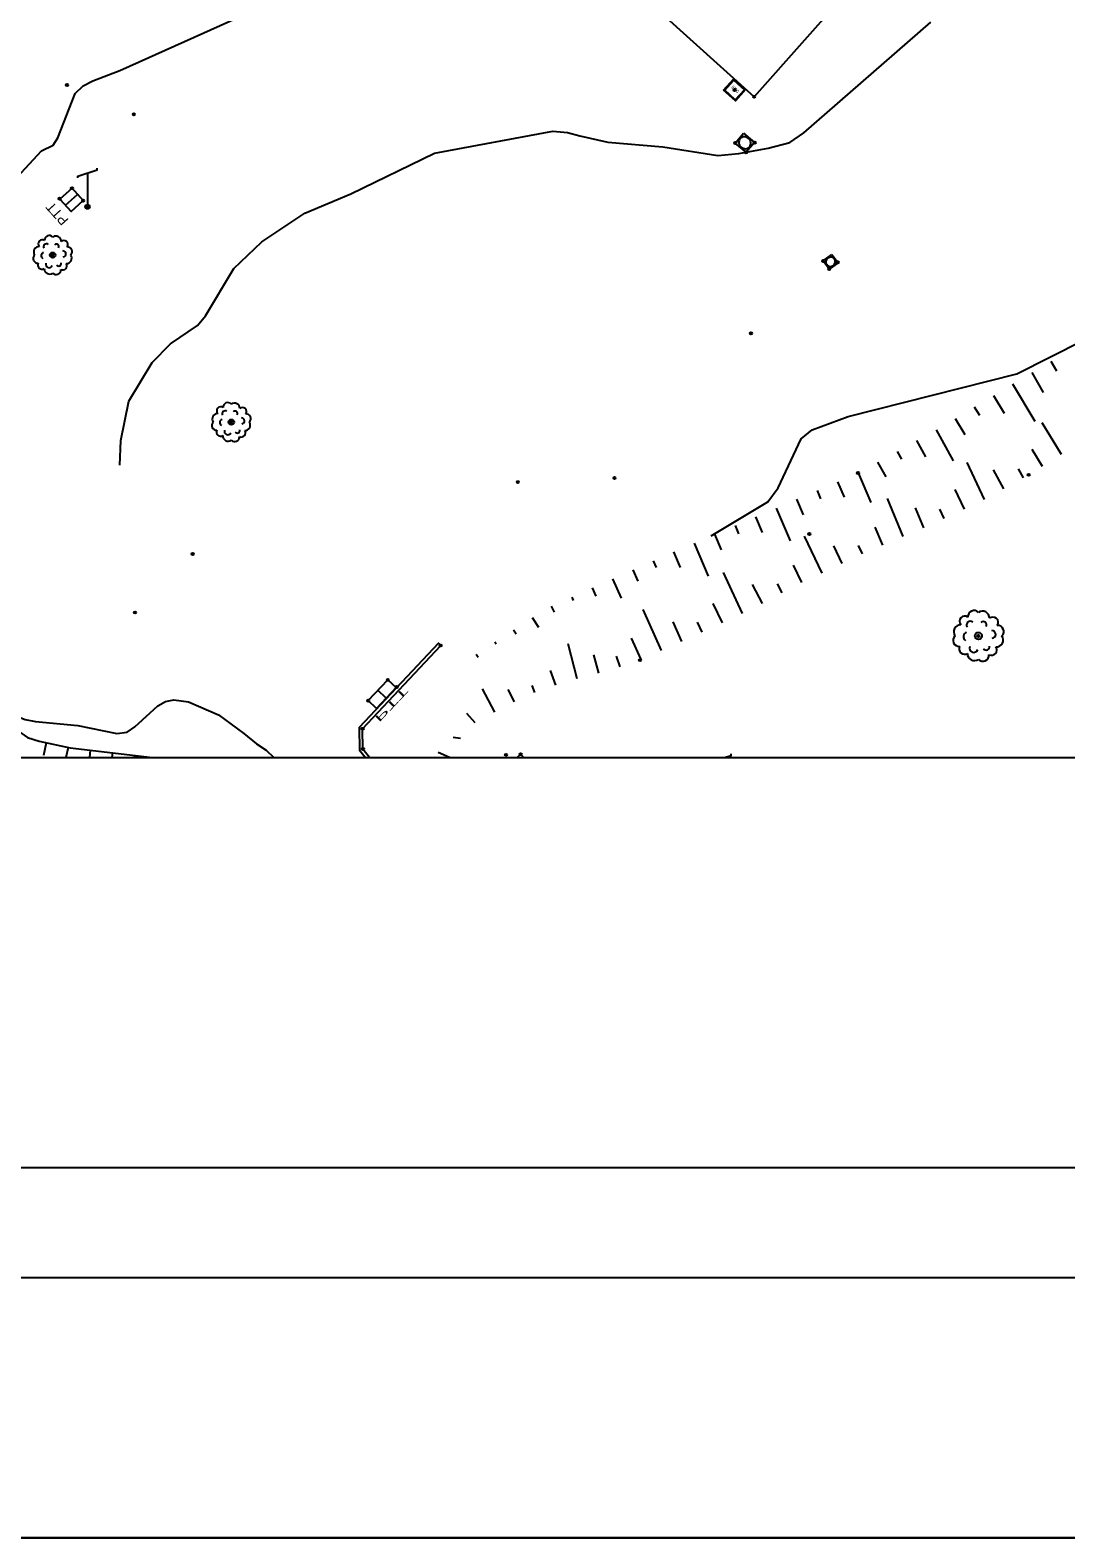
# Model space of a CAD drawing. Extents: x 344013 to 344423, y 298505 to 298795.
# Drawn here: x 344301.3 to 344347.8, y 298504.9 to 298572.5 of the extents above; entities that cross this region are included whole.
import ezdxf

# ---------------------------------------------------------------- set-up
doc = ezdxf.new("R2010")
doc.units = 0
for name, color, linetype in [('Default', 7, 'Continuous'), ('DH_CADRE -CARTOUCHE', 7, 'Continuous'), ('DH_CADRE-CARTOUCHE-NORD', 7, 'Continuous'), ('GO_MUR', 7, 'Continuous'), ('PC_CONCRETE', 7, 'Continuous'), ('RES_ELECTRICITE', 7, 'Continuous'), ('TOPO_COURBE NIVEAU', 7, 'Continuous'), ('TOPO_POINT', 7, 'Continuous'), ('TOPO_TALUS-TERRAIN NATUREL', 7, 'Continuous'), ('VOIRIE_ESPACE VERT', 7, 'Continuous')]:
    doc.layers.add(name, color=color, linetype=linetype)

# ---------------------------------------------------------------- blocks, each defined once
blk = doc.blocks.new('CT2')
at = {"layer": 'Default'}
blk.add_lwpolyline([(0, 0), (1, 0), (1, 1), (0, 1)], close=True, dxfattribs=at)
blk.add_lwpolyline([(0.5, 1), (0.5, 0)], dxfattribs=at)
blk.add_text('PTT', height=0.6, dxfattribs=at).set_placement((-0.3, 1.425))
blk = doc.blocks.new('REG_INC')
at = {"layer": 'Default'}
for p, q in [((0, 1), (1, 1)), ((0, 0), (0, 1)), ((1, 0), (0, 0)), ((1, 1), (1, 0))]:
    blk.add_line(p, q, dxfattribs=at)
for start, end in [(135.0055, 180.0055), (180.0066, 225.0066), (90.0058, 135.0058), (225.0069, 270.0069), (45.0069, 90.0069), (270.0058, 315.0058), (0.0066, 45.0066), (315.0055, 0.0055)]:
    blk.add_arc((0.5, 0.5), 0.44, start, end, dxfattribs=at)
blk = doc.blocks.new('RES_ELECTRICITE')
at = {"layer": 'RES_ELECTRICITE'}
for points in [[(0, 0), (0, 1), (1, 1), (1, 0)], [(0.05, 0.05), (0.05, 0.95), (0.95, 0.95), (0.95, 0.05)]]:
    blk.add_lwpolyline(points, close=True, dxfattribs=at)
blk.add_text('EEC', height=0.2, dxfattribs=at).set_placement((0.237, 0.46))
blk = doc.blocks.new('POINT_DISPLAY')
at = {"layer": 'Default'}
blk.add_circle((0, 0), 0.05, dxfattribs=at)
blk = doc.blocks.new('PTT1')
at = {"layer": 'Default'}
blk.add_line((0, 1.510991), (0, 0.1), dxfattribs=at)
blk.add_lwpolyline([(-0.438601, 1.29169), (-0.438601, 1.36518), (0.438601, 1.656803), (0.438601, 1.730292)], dxfattribs=at)
blk.add_circle((0, 0), 0.1, dxfattribs=at)
blk = doc.blocks.new('ARB1')
at = {"layer": 'Default'}
blk.add_circle((0, 0), 0.122, dxfattribs=at)
for centre, radius, start, end in [((-0.471, 0.503), 0.183, 53.9554, 222.2066), ((-0.153, 0.664), 0.211, 43.6925, 183.5969), ((0.139, 0.613), 0.241, 358.4583, 125.1928), ((0.501, 0.468), 0.183, 325.1444, 131.0175), ((-0.613, 0.139), 0.241, 88.4583, 215.1928), ((-0.373, -0.024), 0.149, 103.7092, 242.3465), ((-0.276, 0.37), 0.134, 52.4396, 209.5496), ((0.164, 0.38), 0.112, 330.5895, 133.7127), ((0.458, 0.052), 0.137, 276.6214, 88.967), ((0.613, -0.139), 0.241, 268.4583, 35.1928), ((0.664, 0.153), 0.211, 313.6925, 93.5969), ((-0.664, -0.153), 0.211, 133.6925, 273.5969), ((-0.478, -0.443), 0.19, 155.2243, 300.9377), ((-0.163, -0.42), 0.148, 159.5371, 338.1663), ((0.271, -0.38), 0.112, 210.5895, 13.7127), ((0.448, -0.483), 0.188, 243.1323, 33.0297), ((-0.139, -0.613), 0.241, 178.4583, 305.1928), ((0.153, -0.664), 0.211, 223.6925, 3.5969)]:
    blk.add_arc(centre, radius, start, end, dxfattribs=at)

msp = doc.modelspace()

# ---------------------------------------------------------------- linework, layer by layer
at = {"layer": 'DH_CADRE -CARTOUCHE'}
for points in [[(344012.906, 298504.876), (344422.906, 298504.876), (344422.906, 298791.876), (344012.906, 298791.876)], [(344222.906, 298539.876), (344422.906, 298539.876), (344422.906, 298504.876), (344222.906, 298504.876)], [(344275.473, 298521.488), (344348.743, 298521.488), (344348.743, 298516.543), (344275.473, 298516.543)]]:
    msp.add_lwpolyline(points, close=True, dxfattribs=at)
msp.add_lwpolyline([(344357.784, 298596.545), (344357.784, 298596.545), (344333.772, 298569.519), (344326.819, 298575.802), (344346.771, 298598.198), (344350.978, 298602.747), (344357.784, 298596.545)], dxfattribs=at)
at = {"layer": 'DH_CADRE-CARTOUCHE-NORD'}
msp.add_lwpolyline([(344332.427, 298539.876), (344332.733, 298539.978), (344332.733, 298540.051)], dxfattribs=at)
at = {"layer": 'GO_MUR'}
for points in [[(344316.513, 298539.876), (344316.217, 298540.259), (344316.198, 298541.169), (344319.708, 298544.905), (344319.599, 298545.008), (344316.047, 298541.227), (344316.068, 298540.207), (344316.324, 298539.876)], [(344323.349, 298539.876), (344323.396, 298539.92), (344323.293, 298540.029), (344323.13, 298539.876)]]:
    msp.add_lwpolyline(points, close=True, dxfattribs=at)
at = {"layer": 'TOPO_COURBE NIVEAU'}
for points in [[(344296.88, 298562.371), (344296.946, 298562.462), (344297.583, 298562.895), (344298.52, 298563.561), (344301.792, 298567.089), (344302.312, 298567.355), (344302.525, 298567.677), (344303.307, 298569.667), (344303.654, 298570.012), (344304.087, 298570.24), (344305.309, 298570.703), (344310.679, 298573.102)], [(344305.31, 298552.993), (344305.343, 298554.095), (344305.716, 298555.866), (344306.75, 298557.603), (344307.585, 298558.435), (344308.798, 298559.267), (344309.152, 298559.699), (344310.422, 298561.814), (344311.676, 298563.015), (344313.606, 298564.296), (344315.668, 298565.173), (344319.426, 298566.985), (344324.731, 298567.984), (344325.393, 298567.919), (344325.943, 298567.761), (344327.209, 298567.484), (344329.68, 298567.275), (344332.141, 298566.886), (344333.085, 298566.979), (344334.407, 298567.212), (344335.367, 298567.463), (344336.006, 298567.895), (344341.693, 298572.872)], [(344331.843, 298549.826), (344334.381, 298551.346), (344334.853, 298551.975), (344335.883, 298554.171), (344336.378, 298554.573), (344337.991, 298555.18), (344345.561, 298557.088), (344351.519, 298560.091)], [(344300.64, 298541.757), (344300.661, 298541.736), (344301.056, 298541.579), (344301.519, 298541.493), (344303.424, 298541.321), (344305.178, 298540.952), (344305.641, 298541.023), (344305.972, 298541.259), (344307.01, 298542.204), (344307.356, 298542.393), (344307.735, 298542.473), (344308.388, 298542.371), (344309.734, 298541.797), (344310.868, 298540.963), (344311.434, 298540.491), (344311.867, 298540.217), (344312.209, 298539.876)]]:
    msp.add_lwpolyline(points, dxfattribs=at)
at = {"layer": 'TOPO_TALUS-TERRAIN NATUREL'}
for p, q in [((344346.226, 298557.149), (344346.746, 298556.259)), ((344347.09, 298557.653), (344347.336, 298557.232)), ((344345.365, 298556.64), (344346.373, 298554.963)), ((344344.508, 298556.125), (344344.986, 298555.329)), ((344342.793, 298555.095), (344343.225, 298554.377)), ((344343.65, 298555.61), (344343.878, 298555.232)), ((344341.934, 298554.583), (344342.706, 298553.191)), ((344347.564, 298553.466), (344346.689, 298554.887)), ((344341.059, 298554.098), (344341.466, 298553.364)), ((344346.712, 298552.942), (344346.251, 298553.69)), ((344339.309, 298553.128), (344339.677, 298552.465)), ((344340.184, 298553.613), (344340.377, 298553.264)), ((344344.11, 298551.448), (344343.329, 298553.121)), ((344338.434, 298552.643), (344339, 298551.32)), ((344344.983, 298551.936), (344344.505, 298552.784)), ((344345.855, 298552.427), (344345.628, 298552.83)), ((344336.595, 298551.856), (344336.752, 298551.488)), ((344337.515, 298552.25), (344337.813, 298551.552)), ((344343.204, 298551.025), (344342.793, 298551.906)), ((344334.756, 298551.069), (344335.387, 298549.594)), ((344335.675, 298551.463), (344335.974, 298550.763)), ((344340.465, 298549.799), (344339.751, 298551.494)), ((344341.387, 298550.187), (344341.01, 298551.082)), ((344342.297, 298550.602), (344342.102, 298551.019)), ((344332.915, 298550.285), (344333.073, 298549.915)), ((344333.836, 298550.677), (344334.134, 298549.975)), ((344331.995, 298549.894), (344332.294, 298549.191)), ((344336.818, 298548.157), (344336.034, 298549.812)), ((344339.543, 298549.411), (344339.205, 298550.214)), ((344330.154, 298549.11), (344330.453, 298548.406)), ((344331.074, 298549.502), (344331.705, 298548.019)), ((344337.722, 298548.585), (344337.349, 298549.371)), ((344338.626, 298549.013), (344338.449, 298549.386)), ((344328.324, 298548.302), (344328.552, 298547.791)), ((344329.238, 298548.709), (344329.371, 298548.41)), ((344335.914, 298547.728), (344335.542, 298548.513)), ((344327.411, 298547.894), (344327.8, 298547.021)), ((344333.251, 298546.346), (344332.393, 298548.182)), ((344334.145, 298546.794), (344333.692, 298547.644)), ((344335.028, 298547.265), (344334.813, 298547.668)), ((344325.583, 298547.08), (344325.654, 298546.921)), ((344326.497, 298547.487), (344326.663, 298547.114)), ((344324.669, 298546.673), (344324.791, 298546.4)), ((344329.614, 298544.679), (344328.79, 298546.521)), ((344332.345, 298545.923), (344331.938, 298546.793)), ((344322.977, 298545.611), (344323.096, 298545.428)), ((344323.815, 298546.157), (344324.093, 298545.73)), ((344330.527, 298545.087), (344330.136, 298545.962)), ((344331.439, 298545.499), (344331.224, 298545.957)), ((344322.139, 298545.065), (344322.189, 298544.987)), ((344325.828, 298543.41), (344325.42, 298544.986)), ((344328.701, 298544.271), (344328.267, 298545.241)), ((344321.3, 298544.52), (344321.387, 298544.386)), ((344326.796, 298543.661), (344326.581, 298544.492)), ((344327.753, 298543.952), (344327.595, 298544.43)), ((344324.868, 298543.132), (344324.639, 298543.787)), ((344322.132, 298541.918), (344321.583, 298542.965)), ((344323.018, 298542.383), (344322.729, 298542.935)), ((344323.924, 298542.801), (344323.815, 298543.112)), ((344321.253, 298541.443), (344320.877, 298541.858)), ((344302.007, 298540.541), (344301.886, 298539.97)), ((344302.986, 298540.333), (344302.889, 298539.876)), ((344303.977, 298540.207), (344303.938, 298539.876)), ((344320.094, 298539.876), (344319.588, 298540.11)), ((344320.591, 298540.729), (344320.267, 298540.776)), ((344304.97, 298540.09), (344304.945, 298539.876)), ((344305.963, 298539.972), (344305.952, 298539.876))]:
    msp.add_line(p, q, dxfattribs=at)
msp.add_lwpolyline([(344261.171, 298586.591), (344261.462, 298586.802), (344261.885, 298586.943), (344262.288, 298586.932), (344262.541, 298586.882), (344262.809, 298586.735), (344279.551, 298570.139), (344295.871, 298554.464), (344296.985, 298553.14), (344298.042, 298551.584), (344299.067, 298549.893), (344299.43, 298549.138), (344299.767, 298548.322), (344300.085, 298546.934), (344300.44, 298543.115), (344300.582, 298541.707), (344300.685, 298541.186), (344300.87, 298540.983), (344301.161, 298540.78), (344301.681, 298540.61), (344303.077, 298540.314), (344306.776, 298539.876)], dxfattribs=at)

# ---------------------------------------------------------------- block references
at = {"layer": 'DH_CADRE-CARTOUCHE-NORD'}
msp.add_blockref('PTT1', (344303.857, 298564.587), dxfattribs=at)
for p, xscale, yscale, rotation in [((344303.659, 298564.86), 0.749131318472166, 0.7295833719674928, 131.86188), ((344316.449, 298542.431), 1.285793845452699, -0.5121189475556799, 46.668599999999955)]:
    msp.add_blockref('CT2', p, dxfattribs=dict(at, xscale=xscale, yscale=yscale, rotation=rotation))
at = {"layer": 'PC_CONCRETE'}
for p, xscale, yscale, rotation in [((344332.923, 298567.443), 0.6348729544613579, 0.58012684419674, -40.56129), ((344336.868, 298562.158), 0.46101483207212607, 0.48972703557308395, -54.04230000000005)]:
    msp.add_blockref('REG_INC', p, dxfattribs=dict(at, xscale=xscale, yscale=yscale, rotation=rotation))
at = {"layer": 'RES_ELECTRICITE', "xscale": 0.7140719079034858, "yscale": 0.6822477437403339, "rotation": -42.26805488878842}
msp.add_blockref('RES_ELECTRICITE', (344332.399, 298569.815), dxfattribs=at)
at = {"layer": 'TOPO_POINT'}
for p in [(344302.937, 298570.048), (344332.893, 298569.827), (344333.772, 298569.519), (344305.934, 298568.734), (344332.923, 298567.443), (344333.797, 298567.458), (344333.405, 298567.03), (344303.159, 298565.418), (344302.601, 298564.947), (344303.659, 298564.86), (344303.857, 298564.587), (344302.293, 298562.419), (344336.868, 298562.158), (344337.139, 298561.785), (344337.52, 298562.093), (344333.629, 298558.907), (344310.307, 298554.927), (344323.166, 298552.234), (344327.506, 298552.421), (344338.435, 298552.643), (344346.092, 298552.56), (344336.252, 298549.907), (344308.577, 298549.005), (344305.987, 298546.387), (344319.708, 298544.905), (344343.836, 298545.336), (344328.651, 298544.248), (344317.331, 298543.366), (344317.73, 298543.042), (344316.449, 298542.431), (344316.198, 298541.169), (344316.217, 298540.259), (344322.636, 298540.002), (344323.293, 298540.029)]:
    msp.add_blockref('POINT_DISPLAY', p, dxfattribs=at)
at = {"layer": 'VOIRIE_ESPACE VERT'}
for p in [(344302.293, 298562.419), (344310.307, 298554.927)]:
    msp.add_blockref('ARB1', p, dxfattribs=at)
at = {"layer": 'VOIRIE_ESPACE VERT', "xscale": 1.3, "yscale": 1.3}
msp.add_blockref('ARB1', (344343.836, 298545.336), dxfattribs=at)

doc.saveas('drawing.dxf')
